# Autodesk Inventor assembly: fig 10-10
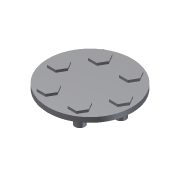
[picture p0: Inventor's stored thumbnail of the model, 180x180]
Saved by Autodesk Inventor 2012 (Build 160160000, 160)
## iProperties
Created: 2008-05
Part Number: fig 10-10
Document SubType Name: Assembly
Designer: CADCIM
Author: CADCIM
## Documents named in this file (3)
- C:\Users\CadCim\Documents\SAILESH\inventor-2011-fact-prt\c10-inv-2011-prt\c10_inv_2012_prt\fig 10-10.iam
- C:\Users\CadCim\Documents\SAILESH\inventor-2011-fact-prt\c10-inv-2011-prt\c10_inv_2012_prt\Part4.ipt
- C:\Users\CadCim\Documents\SAILESH\inventor-2011-fact-prt\c10-inv-2011-prt\c10_inv_2012_prt\Part5.ipt
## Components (7 placed, 2 different names)
1. Part4:1
2. Part5:1
3. Part5:2
4. Part5:3
5. Part5:4
6. Part5:5
7. Part5:6
